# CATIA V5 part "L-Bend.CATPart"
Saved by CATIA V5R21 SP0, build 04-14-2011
Part number: L-Bend
Bounding box of the stored display mesh (mm): x -50 to 50, y -130 to 15, z -50 to 100
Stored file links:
  D:\CATIA V5R21 E-RESOURCES\CATIA-V5R21\catia-v5r21-Prts\c12_catia_v5r21_prt\c12_catia_v5r21figr_12-39\L-Bend.CATPart
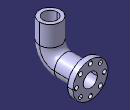
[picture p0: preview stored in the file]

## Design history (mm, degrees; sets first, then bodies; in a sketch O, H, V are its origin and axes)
Body1 (main body)
  Sketch1 on yz-plane, origin (0, 0, 0), H (0, 1, 0), V (0, 0, 1)
    line L1 (0, 0) -> (-57.4642, 0)
    point P1 (-100, 0)
    line L2 (-100, 42.5358) -> (-100, 100)
    point P2 (-100, 100)
    arc A1 centre (-57.4642, 42.5358) radius 42.5358 from (-100, 42.5358) to (-57.4642, 0) ccw
    distance P1 P2 = 100
    distance O P1 = 100
    radius A1 = 42.5358
    horizontal: L1 H
    vertical: L2 V
    coincidence: L2 P1, L1 P1
    tangency: A1 L2, A1 L1
  Sketch2 on zx-plane, origin (0, 0, 0), H (-1, 0, 0), V (0, 0, 1)
    circle A1 centre (0, 0) radius 30
    point P1 (0, -30)
    radius A1 = 30
    coincidence: A1 P1, P1 V
  Rib1: profile Sketch2, centre curve Sketch1
  Shell1: ExtOffset 0, Face (face of Rib1; face of Rib1), IntOffset 10
  Sketch3 on face of Rib1, origin (0, 0, 0), H (-1, 0, 0), V (0, 0, 1)
    circle A1 centre (0, 0) radius 50
    point P1 (0, -50)
    projected circle E1 centre (0, 0) radius 20 from edge [face of Shell1 | face of Rib1]
    radius A1 = 50
    coincidence: A1 P1, P1 V
  Pad1: profile Sketch3, direction (0, 1, 0), length 15
  Sketch4 on face of Pad1, origin (0, 15, 0), H (-1, 0, 0), V (0, 0, 1)
    circle A1 centre (0, -40) radius 6
    point P1 (0, -40)
    radius A1 = 6
    distance H P1 = 40
    coincidence: P1 V
  Pocket1: profile Sketch4, direction (0, -1, 0), length 15
  CircPattern1: of Pocket1, instances 8, angular step 45, axis from face of Pad1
